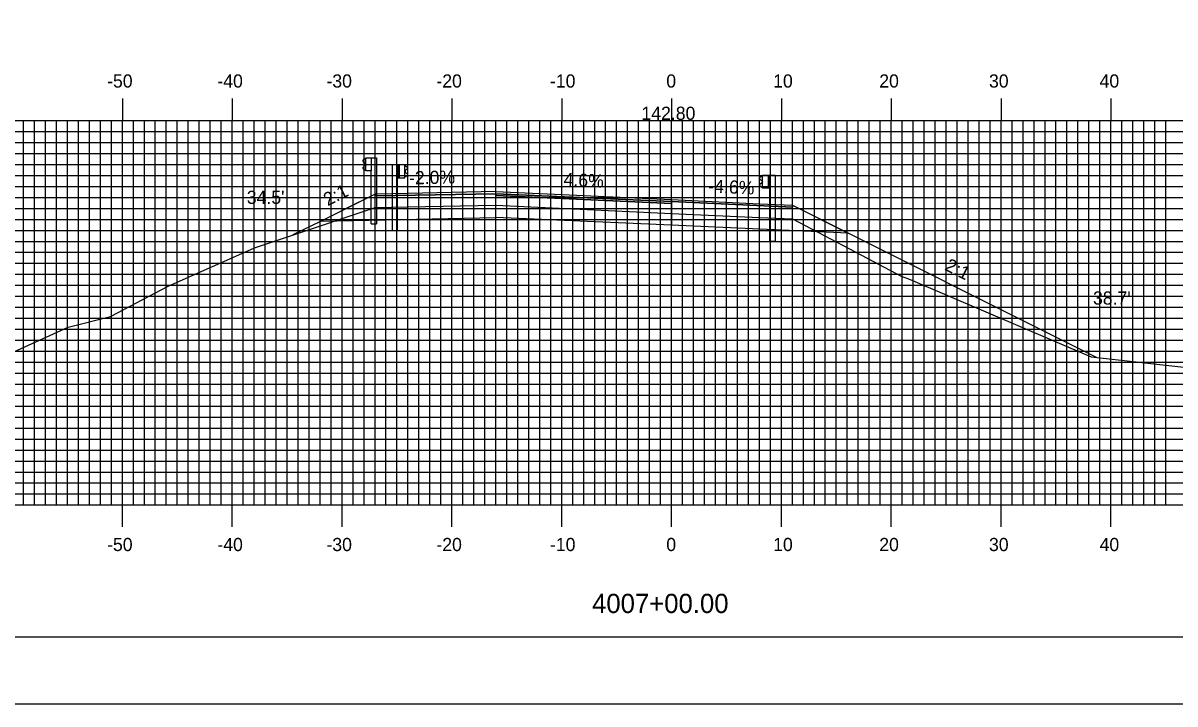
# Model space of a CAD drawing. Extents: x 851753 to 852097, y 364661 to 364881.
# Drawn here: x 851860.2 to 851965.1, y 364661.3 to 364723.2 of the extents above; entities that cross this region are included whole.
import ezdxf

# ---------------------------------------------------------------- set-up
doc = ezdxf.new("R2010")
doc.units = 0
for name, color, linetype in [('ANNOTATION', 7, 'Continuous'), ('BORDER', 7, 'Continuous'), ('D_Guardrail_Beam_Lt', 7, 'Continuous'), ('D_Guardrail_Beam_Rt', 7, 'Continuous'), ('D_Roadway_Centerline_Text', 7, 'Continuous'), ('D_Roadway_Edge_Shoulder', 7, 'Continuous'), ('D_Roadway_Edge_TW', 7, 'Continuous'), ('D_Roadway_Pavement', 7, 'Continuous'), ('D_Roadway_SlopeLines', 7, 'Continuous'), ('D_Roadway_SubGrade', 7, 'Continuous'), ('D_Text_Standard', 7, 'Continuous'), ('H_V ANNOTATION', 7, 'Continuous'), ('M_Guardrail', 7, 'Continuous'), ('M_Roadway_Centerline', 7, 'Continuous'), ('MAJOR', 7, 'Continuous'), ('MINOR', 7, 'Continuous'), ('PLOT BOUNDARY', 7, 'Continuous'), ('S_Roadway_Centerline', 7, 'Continuous')]:
    doc.layers.add(name, color=color, linetype=linetype)

msp = doc.modelspace()

# ---------------------------------------------------------------- linework, layer by layer
at = {"layer": 'BORDER'}
msp.add_lwpolyline([(851769.64, 364667.37), (852089.64, 364667.37), (852089.64, 364877.37), (851769.64, 364877.37)], close=True, dxfattribs=at)
at = {"layer": 'D_Guardrail_Beam_Lt'}
for p, q in [((851893.81, 364710.33), (851893.81, 364704.33)), ((851894.28, 364710.33), (851893.81, 364710.33)), ((851894.97, 364710.33), (851894.28, 364710.33)), ((851894.28, 364710.33), (851894.28, 364709.16)), ((851894.35, 364710.33), (851894.35, 364709.16)), ((851894.45, 364710.33), (851894.45, 364709.16)), ((851894.97, 364709.16), (851894.97, 364710.33)), ((851894.97, 364710.24), (851895.05, 364710.23)), ((851894.98, 364709.78), (851894.98, 364709.71)), ((851895.2, 364709.98), (851895.01, 364709.84)), ((851895.01, 364709.64), (851895.2, 364709.51)), ((851895.06, 364710.22), (851895.2, 364710.12)), ((851894.28, 364709.16), (851894.97, 364709.16)), ((851894.3, 364704.33), (851894.3, 364709.16)), ((851895.05, 364709.26), (851894.97, 364709.24)), ((851895.2, 364709.36), (851895.06, 364709.26)), ((851894.3, 364704.33), (851893.81, 364704.33))]:
    msp.add_line(p, q, dxfattribs=at)
for centre, major_axis, start_param, end_param in [((851895.05, 364709.78), (-0.0789, 0), 5.323254, 6.283185), ((851895.05, 364709.71), (-0.0789, 0), 6.283185, 7.243116), ((851895.04, 364710.19), (0.0417, 0), 0.959931, 1.376053), ((851895.15, 364710.05), (0.0877, 0), 5.323254, 7.243116), ((851895.15, 364709.44), (0.0877, 0), 5.323254, 7.243116), ((851895.04, 364709.3), (0.0417, 0), 4.907132, 5.323254)]:
    msp.add_ellipse(centre, major_axis=major_axis, ratio=0.995501, start_param=start_param, end_param=end_param, dxfattribs=at)
at = {"layer": 'D_Guardrail_Beam_Rt'}
for p, q in [((851927.42, 364709.28), (851927.28, 364709.18)), ((851927.28, 364709.03), (851927.47, 364708.9)), ((851927.47, 364708.7), (851927.28, 364708.56)), ((851927.51, 364709.3), (851927.44, 364709.28)), ((851927.51, 364709.38), (851928.2, 364709.38)), ((851927.51, 364708.22), (851927.51, 364709.38)), ((851927.51, 364708.83), (851927.51, 364708.76)), ((851928.03, 364709.38), (851928.03, 364708.22)), ((851928.14, 364709.38), (851928.14, 364708.22)), ((851928.2, 364709.38), (851928.67, 364709.38)), ((851928.2, 364709.38), (851928.2, 364708.22)), ((851928.67, 364709.38), (851928.67, 364703.38)), ((851927.28, 364708.42), (851927.42, 364708.32)), ((851927.44, 364708.31), (851927.51, 364708.3)), ((851928.2, 364708.22), (851927.51, 364708.22)), ((851928.18, 364703.38), (851928.18, 364708.22)), ((851928.18, 364703.38), (851928.67, 364703.38))]:
    msp.add_line(p, q, dxfattribs=at)
for centre, major_axis, start_param, end_param in [((851927.33, 364709.11), (-0.0877, 0), 5.323254, 7.243116), ((851927.33, 364708.49), (-0.0877, 0), 5.323254, 7.243116), ((851927.45, 364709.24), (-0.0417, 0), 4.907132, 5.323254), ((851927.43, 364708.83), (0.0789, 0), 0, 0.959931), ((851927.43, 364708.76), (0.0789, 0), 5.323254, 6.283185), ((851927.45, 364708.35), (-0.0417, 0), 0.959931, 1.376053)]:
    msp.add_ellipse(centre, major_axis=major_axis, ratio=0.995501, start_param=start_param, end_param=end_param, dxfattribs=at)
at = {"layer": 'D_Roadway_Edge_Shoulder'}
for points in [[(851903.24, 364707.9), (851895.24, 364707.74), (851895.24, 364707.74), (851892.24, 364707.68), (851892.24, 364707.52), (851903.24, 364707.71)], [(851919.24, 364707.17), (851927.24, 364706.8), (851927.24, 364706.8), (851930.24, 364706.66), (851930.24, 364706.49), (851919.24, 364707)]]:
    msp.add_lwpolyline(points, close=True, dxfattribs=at)
at = {"layer": 'D_Roadway_Edge_TW'}
msp.add_lwpolyline([(851903.24, 364707.9), (851919.24, 364707.17), (851919.24, 364707), (851903.24, 364707.71)], close=True, dxfattribs=at)
at = {"layer": 'D_Roadway_Pavement'}
msp.add_lwpolyline([(851903.24, 364707.71), (851919.24, 364707), (851919.24, 364706.83), (851903.24, 364707.54)], close=True, dxfattribs=at)
for points in [[(851903.24, 364707.71), (851903.24, 364707.54)], [(851919.24, 364707), (851919.24, 364706.83)], [(851919.24, 364707), (851919.24, 364706.83)], [(851919.24, 364707), (851919.24, 364706.83)]]:
    msp.add_lwpolyline(points, dxfattribs=at)
at = {"layer": 'D_Roadway_SlopeLines'}
for points in [[(851892.24, 364707.68), (851889.37, 364706.25)], [(851930.24, 364706.66), (851957.96, 364692.8)]]:
    msp.add_lwpolyline(points, dxfattribs=at)
at = {"layer": 'D_Roadway_SubGrade'}
msp.add_line((851887.33, 364705.22), (851884.77, 364703.95), dxfattribs=at)
for points in [[(851903.24, 364707.54), (851903.24, 364707.71), (851892.24, 364707.52), (851892.24, 364707.68), (851887.33, 364705.22), (851903.24, 364705.54)], [(851903.24, 364707.54), (851919.24, 364706.83), (851919.24, 364704.83), (851903.24, 364705.54)], [(851919.24, 364706.83), (851919.24, 364707), (851930.24, 364706.49), (851930.24, 364706.66), (851935.32, 364704.12), (851919.24, 364704.83)]]:
    msp.add_lwpolyline(points, close=True, dxfattribs=at)
at = {"layer": 'M_Guardrail'}
for p, q in [((851891.31, 364710.87), (851891.16, 364710.77)), ((851891.16, 364710.63), (851891.36, 364710.49)), ((851891.41, 364710.89), (851891.32, 364710.88)), ((851891.41, 364710.96), (851891.9, 364710.96)), ((851891.41, 364709.8), (851891.41, 364710.96)), ((851891.9, 364710.96), (851892.39, 364710.96)), ((851891.9, 364710.96), (851891.9, 364709.8)), ((851892.39, 364710.96), (851892.39, 364704.96)), ((851891.36, 364710.27), (851891.16, 364710.14)), ((851891.16, 364709.99), (851891.31, 364709.89)), ((851891.32, 364709.89), (851891.41, 364709.87)), ((851891.39, 364710.43), (851891.39, 364710.34)), ((851891.9, 364709.8), (851891.41, 364709.8)), ((851891.9, 364704.96), (851891.9, 364709.8)), ((851891.9, 364704.96), (851892.39, 364704.96))]:
    msp.add_line(p, q, dxfattribs=at)
for centre, major_axis, start_param, end_param in [((851891.21, 364710.7), (-0.0877, 0), 5.323254, 7.243116), ((851891.33, 364710.84), (-0.0417, 0), 4.886922, 5.323254), ((851891.21, 364710.06), (-0.0877, 0), 5.323254, 7.243116), ((851891.33, 364709.93), (-0.0417, 0), 0.959931, 1.396263), ((851891.31, 364710.43), (0.0789, 0), 0, 0.959931), ((851891.31, 364710.34), (0.0789, 0), 5.323254, 6.283185)]:
    msp.add_ellipse(centre, major_axis=major_axis, ratio=0.995501, start_param=start_param, end_param=end_param, dxfattribs=at)
at = {"layer": 'MAJOR'}
for p, q in [((851869.24, 364716.37), (851869.24, 364714.37)), ((851879.24, 364716.37), (851879.24, 364714.37)), ((851889.24, 364716.37), (851889.24, 364714.37)), ((851899.24, 364716.37), (851899.24, 364714.37)), ((851909.24, 364716.37), (851909.24, 364714.37)), ((851919.24, 364716.37), (851919.24, 364714.37)), ((851929.24, 364716.37), (851929.24, 364714.37)), ((851939.24, 364716.37), (851939.24, 364714.37)), ((851949.24, 364716.37), (851949.24, 364714.37)), ((851959.24, 364716.37), (851959.24, 364714.37)), ((851779.24, 364714.37), (852059.24, 364714.37)), ((851779.24, 364714.37), (852059.24, 364714.37)), ((851869.24, 364679.37), (851869.24, 364714.37)), ((851879.24, 364679.37), (851879.24, 364714.37)), ((851889.24, 364679.37), (851889.24, 364714.37)), ((851899.24, 364679.37), (851899.24, 364714.37)), ((851909.24, 364679.37), (851909.24, 364714.37)), ((851919.24, 364679.37), (851919.24, 364714.37)), ((851929.24, 364679.37), (851929.24, 364714.37)), ((851939.24, 364679.37), (851939.24, 364714.37)), ((851949.24, 364679.37), (851949.24, 364714.37)), ((851959.24, 364679.37), (851959.24, 364714.37)), ((851779.24, 364709.37), (852059.24, 364709.37)), ((851779.24, 364704.37), (852059.24, 364704.37)), ((851779.24, 364699.37), (852059.24, 364699.37)), ((851779.24, 364694.37), (852059.24, 364694.37)), ((851779.24, 364689.37), (852059.24, 364689.37)), ((851779.24, 364684.37), (852059.24, 364684.37)), ((851779.24, 364679.37), (852059.24, 364679.37)), ((851779.24, 364679.37), (852059.24, 364679.37)), ((851869.24, 364677.37), (851869.24, 364679.37)), ((851879.24, 364677.37), (851879.24, 364679.37)), ((851889.24, 364677.37), (851889.24, 364679.37)), ((851899.24, 364677.37), (851899.24, 364679.37)), ((851909.24, 364677.37), (851909.24, 364679.37)), ((851919.24, 364677.37), (851919.24, 364679.37)), ((851929.24, 364677.37), (851929.24, 364679.37)), ((851939.24, 364677.37), (851939.24, 364679.37)), ((851949.24, 364677.37), (851949.24, 364679.37)), ((851959.24, 364677.37), (851959.24, 364679.37))]:
    msp.add_line(p, q, dxfattribs=at)
at = {"layer": 'MINOR'}
for p, q in [((851860.24, 364679.37), (851860.24, 364714.37)), ((851861.24, 364679.37), (851861.24, 364714.37)), ((851862.24, 364679.37), (851862.24, 364714.37)), ((851863.24, 364679.37), (851863.24, 364714.37)), ((851864.24, 364679.37), (851864.24, 364714.37)), ((851865.24, 364679.37), (851865.24, 364714.37)), ((851866.24, 364679.37), (851866.24, 364714.37)), ((851867.24, 364679.37), (851867.24, 364714.37)), ((851868.24, 364679.37), (851868.24, 364714.37)), ((851870.24, 364679.37), (851870.24, 364714.37)), ((851871.24, 364679.37), (851871.24, 364714.37)), ((851872.24, 364679.37), (851872.24, 364714.37)), ((851873.24, 364679.37), (851873.24, 364714.37)), ((851874.24, 364679.37), (851874.24, 364714.37)), ((851875.24, 364679.37), (851875.24, 364714.37)), ((851876.24, 364679.37), (851876.24, 364714.37)), ((851877.24, 364679.37), (851877.24, 364714.37)), ((851878.24, 364679.37), (851878.24, 364714.37)), ((851880.24, 364679.37), (851880.24, 364714.37)), ((851881.24, 364679.37), (851881.24, 364714.37)), ((851882.24, 364679.37), (851882.24, 364714.37)), ((851883.24, 364679.37), (851883.24, 364714.37)), ((851884.24, 364679.37), (851884.24, 364714.37)), ((851885.24, 364679.37), (851885.24, 364714.37)), ((851886.24, 364679.37), (851886.24, 364714.37)), ((851887.24, 364679.37), (851887.24, 364714.37)), ((851888.24, 364679.37), (851888.24, 364714.37)), ((851890.24, 364679.37), (851890.24, 364714.37)), ((851891.24, 364679.37), (851891.24, 364714.37)), ((851892.24, 364679.37), (851892.24, 364714.37)), ((851893.24, 364679.37), (851893.24, 364714.37)), ((851894.24, 364679.37), (851894.24, 364714.37)), ((851895.24, 364679.37), (851895.24, 364714.37)), ((851896.24, 364679.37), (851896.24, 364714.37)), ((851897.24, 364679.37), (851897.24, 364714.37)), ((851898.24, 364679.37), (851898.24, 364714.37)), ((851900.24, 364679.37), (851900.24, 364714.37)), ((851901.24, 364679.37), (851901.24, 364714.37)), ((851902.24, 364679.37), (851902.24, 364714.37)), ((851903.24, 364679.37), (851903.24, 364714.37)), ((851904.24, 364679.37), (851904.24, 364714.37)), ((851905.24, 364679.37), (851905.24, 364714.37)), ((851906.24, 364679.37), (851906.24, 364714.37)), ((851907.24, 364679.37), (851907.24, 364714.37)), ((851908.24, 364679.37), (851908.24, 364714.37)), ((851910.24, 364679.37), (851910.24, 364714.37)), ((851911.24, 364679.37), (851911.24, 364714.37)), ((851912.24, 364679.37), (851912.24, 364714.37)), ((851913.24, 364679.37), (851913.24, 364714.37)), ((851914.24, 364679.37), (851914.24, 364714.37)), ((851915.24, 364679.37), (851915.24, 364714.37)), ((851916.24, 364679.37), (851916.24, 364714.37)), ((851917.24, 364679.37), (851917.24, 364714.37)), ((851918.24, 364679.37), (851918.24, 364714.37)), ((851920.24, 364679.37), (851920.24, 364714.37)), ((851921.24, 364679.37), (851921.24, 364714.37)), ((851922.24, 364679.37), (851922.24, 364714.37)), ((851923.24, 364679.37), (851923.24, 364714.37)), ((851924.24, 364679.37), (851924.24, 364714.37)), ((851925.24, 364679.37), (851925.24, 364714.37)), ((851926.24, 364679.37), (851926.24, 364714.37)), ((851927.24, 364679.37), (851927.24, 364714.37)), ((851928.24, 364679.37), (851928.24, 364714.37)), ((851930.24, 364679.37), (851930.24, 364714.37)), ((851931.24, 364679.37), (851931.24, 364714.37)), ((851932.24, 364679.37), (851932.24, 364714.37)), ((851933.24, 364679.37), (851933.24, 364714.37)), ((851934.24, 364679.37), (851934.24, 364714.37)), ((851935.24, 364679.37), (851935.24, 364714.37)), ((851936.24, 364679.37), (851936.24, 364714.37)), ((851937.24, 364679.37), (851937.24, 364714.37)), ((851938.24, 364679.37), (851938.24, 364714.37)), ((851940.24, 364679.37), (851940.24, 364714.37)), ((851941.24, 364679.37), (851941.24, 364714.37)), ((851942.24, 364679.37), (851942.24, 364714.37)), ((851943.24, 364679.37), (851943.24, 364714.37)), ((851944.24, 364679.37), (851944.24, 364714.37)), ((851945.24, 364679.37), (851945.24, 364714.37)), ((851946.24, 364679.37), (851946.24, 364714.37)), ((851947.24, 364679.37), (851947.24, 364714.37)), ((851948.24, 364679.37), (851948.24, 364714.37)), ((851950.24, 364679.37), (851950.24, 364714.37)), ((851951.24, 364679.37), (851951.24, 364714.37)), ((851952.24, 364679.37), (851952.24, 364714.37)), ((851953.24, 364679.37), (851953.24, 364714.37)), ((851954.24, 364679.37), (851954.24, 364714.37)), ((851955.24, 364679.37), (851955.24, 364714.37)), ((851956.24, 364679.37), (851956.24, 364714.37)), ((851957.24, 364679.37), (851957.24, 364714.37)), ((851958.24, 364679.37), (851958.24, 364714.37)), ((851960.24, 364679.37), (851960.24, 364714.37)), ((851961.24, 364679.37), (851961.24, 364714.37)), ((851962.24, 364679.37), (851962.24, 364714.37)), ((851963.24, 364679.37), (851963.24, 364714.37)), ((851964.24, 364679.37), (851964.24, 364714.37)), ((851779.24, 364713.37), (852059.24, 364713.37)), ((851779.24, 364712.37), (852059.24, 364712.37)), ((851779.24, 364711.37), (852059.24, 364711.37)), ((851779.24, 364710.37), (852059.24, 364710.37)), ((851779.24, 364708.37), (852059.24, 364708.37)), ((851779.24, 364707.37), (852059.24, 364707.37)), ((851779.24, 364706.37), (852059.24, 364706.37)), ((851779.24, 364705.37), (852059.24, 364705.37)), ((851779.24, 364703.37), (852059.24, 364703.37)), ((851779.24, 364702.37), (852059.24, 364702.37)), ((851779.24, 364701.37), (852059.24, 364701.37)), ((851779.24, 364700.37), (852059.24, 364700.37)), ((851779.24, 364698.37), (852059.24, 364698.37)), ((851779.24, 364697.37), (852059.24, 364697.37)), ((851779.24, 364696.37), (852059.24, 364696.37)), ((851779.24, 364695.37), (852059.24, 364695.37)), ((851779.24, 364693.37), (852059.24, 364693.37)), ((851779.24, 364692.37), (852059.24, 364692.37)), ((851779.24, 364691.37), (852059.24, 364691.37)), ((851779.24, 364690.37), (852059.24, 364690.37)), ((851779.24, 364688.37), (852059.24, 364688.37)), ((851779.24, 364687.37), (852059.24, 364687.37)), ((851779.24, 364686.37), (852059.24, 364686.37)), ((851779.24, 364685.37), (852059.24, 364685.37)), ((851779.24, 364683.37), (852059.24, 364683.37)), ((851779.24, 364682.37), (852059.24, 364682.37)), ((851779.24, 364681.37), (852059.24, 364681.37)), ((851779.24, 364680.37), (852059.24, 364680.37))]:
    msp.add_line(p, q, dxfattribs=at)
at = {"layer": 'PLOT BOUNDARY'}
msp.add_lwpolyline([(851753.46, 364661.25), (852093.46, 364661.25), (852093.46, 364881.25), (851753.46, 364881.25)], close=True, dxfattribs=at)
at = {"layer": 'S_Roadway_Centerline'}
msp.add_line((851887.33, 364705.22), (851884.77, 364703.95), dxfattribs=at)
for points in [[(851881.25, 364702.78), (851881.26, 364702.78), (851884.26, 364703.78), (851892.24, 364706.44), (851895.24, 364706.5), (851903.24, 364706.66), (851919.24, 364705.92), (851927.24, 364705.55), (851930.24, 364705.42), (851935.45, 364702.68), (851940.2, 364700.18)], [(851779.24, 364684.71), (851782.62, 364684.78), (851791.54, 364684.99), (851800.46, 364685.43), (851810.63, 364686.3), (851817.6, 364686.24), (851831.58, 364686.78), (851834.69, 364686.89), (851836.07, 364686.94), (851851.43, 364689.74), (851864.3, 364695.56), (851868.15, 364696.54), (851873.42, 364699.29), (851881.21, 364702.76)], [(851940.2, 364700.18), (851940.49, 364700.08), (851940.56, 364700.06), (851940.95, 364699.91), (851957.44, 364692.86), (851965.87, 364691.92), (851977.86, 364690.69), (851987.91, 364690.56), (851992.17, 364690.5), (852003.7, 364690.4), (852008.58, 364690.52), (852022.99, 364690.23), (852023.93, 364690.19), (852024.96, 364690.42), (852029.08, 364691.28), (852042.76, 364693.52), (852054.82, 364694.96), (852059.24, 364695.34)]]:
    msp.add_lwpolyline(points, dxfattribs=at)

# ---------------------------------------------------------------- texts
at = {"layer": 'ANNOTATION'}
for s, rotation, p in [('-2.0%', 1.1458, (851895.35, 364708.55)), ('4.6%', 357.3663, (851909.39, 364708.42)), ('2:1', 26.5651, (851887.93, 364706.56)), ('-4.6%', 357.3663, (851922.57, 364707.82)), ('2:1', 333.4349, (851944.03, 364700.8))]:
    msp.add_text(s, height=1.2, rotation=rotation, dxfattribs=at).set_placement(p)
at = {"layer": 'D_Roadway_Centerline_Text'}
msp.add_text('142.80', height=1.2, dxfattribs=at).set_placement((851916.5, 364714.43))
at = {"layer": 'D_Text_Standard'}
for s, p in [("34.5'", (851880.57, 364706.78)), ("38.7'", (851957.61, 364697.61))]:
    msp.add_text(s, height=1.2, dxfattribs=at).set_placement(p)
at = {"layer": 'H_V ANNOTATION'}
for s, height, p in [('-50', 1.2, (851867.85, 364717.37)), ('-40', 1.2, (851877.89, 364717.37)), ('-30', 1.2, (851887.82, 364717.37)), ('-20', 1.2, (851897.83, 364717.37)), ('-10', 1.2, (851908.17, 364717.37)), ('0', 1.2, (851918.76, 364717.37)), ('10', 1.2, (851928.49, 364717.37)), ('20', 1.2, (851938.15, 364717.37)), ('30', 1.2, (851948.14, 364717.37)), ('40', 1.2, (851958.21, 364717.37)), ('-50', 1.2, (851867.85, 364675.17)), ('-40', 1.2, (851877.89, 364675.17)), ('-30', 1.2, (851887.82, 364675.17)), ('-20', 1.2, (851897.83, 364675.17)), ('-10', 1.2, (851908.17, 364675.17)), ('0', 1.2, (851918.76, 364675.17)), ('10', 1.2, (851928.49, 364675.17)), ('20', 1.2, (851938.15, 364675.17)), ('30', 1.2, (851948.14, 364675.17)), ('40', 1.2, (851958.21, 364675.17)), ('4007+00.00', 1.75, (851912, 364669.53))]:
    msp.add_text(s, height=height, dxfattribs=at).set_placement(p)
at = {"layer": 'M_Roadway_Centerline'}
for s, p in [('C', (851905.72, 364706.15)), ('L', (851905.73, 364706.14))]:
    msp.add_text(s, height=0.0146, dxfattribs=at).set_placement(p)

doc.saveas('drawing.dxf')
